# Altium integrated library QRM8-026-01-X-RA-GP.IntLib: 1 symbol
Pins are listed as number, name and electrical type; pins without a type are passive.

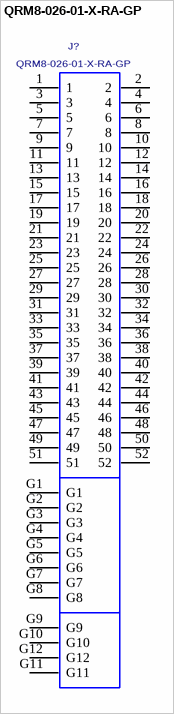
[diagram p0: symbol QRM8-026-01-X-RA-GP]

## QRM8-026-01-X-RA-GP
designator J?
.8mm Q-Rate  Right Angle Terminal  Assembly.; MANUFACTURER: SAMTEC
footprint QRM8-026-01-X-RA-GP
pins: 1, 2, 3, 4, 5, 6, 7, 8, 9, 10, 11, 12, 13, 14, 15, 16, 17, 18, 19, 20, 21, 22, 23, 24, 25, 26, 27, 28, 29, 30, 31, 32, 33, 34, 35, 36, 37, 38, 39, 40, 41, 42, 43, 44, 45, 46, 47, 48, 49, 50, 51, 52, G1, G2, G3, G4, G5, G6, G7, G8, G9, G10, G11, G12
